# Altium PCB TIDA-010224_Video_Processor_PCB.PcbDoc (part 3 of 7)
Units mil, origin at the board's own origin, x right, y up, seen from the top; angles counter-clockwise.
Board outline 2355.46 x 4164 mil, 10 copper layers (L1-Top Layer, L2-GND, L3-SIG1, L4-GND, L5-PWR, L6-PWR, L7-GND, L8-SIG2, L9-GND, L10-Bottom Layer), stack 62.2 mil thick; 508 components, 274 nets, 3619 pads, 705 vias.
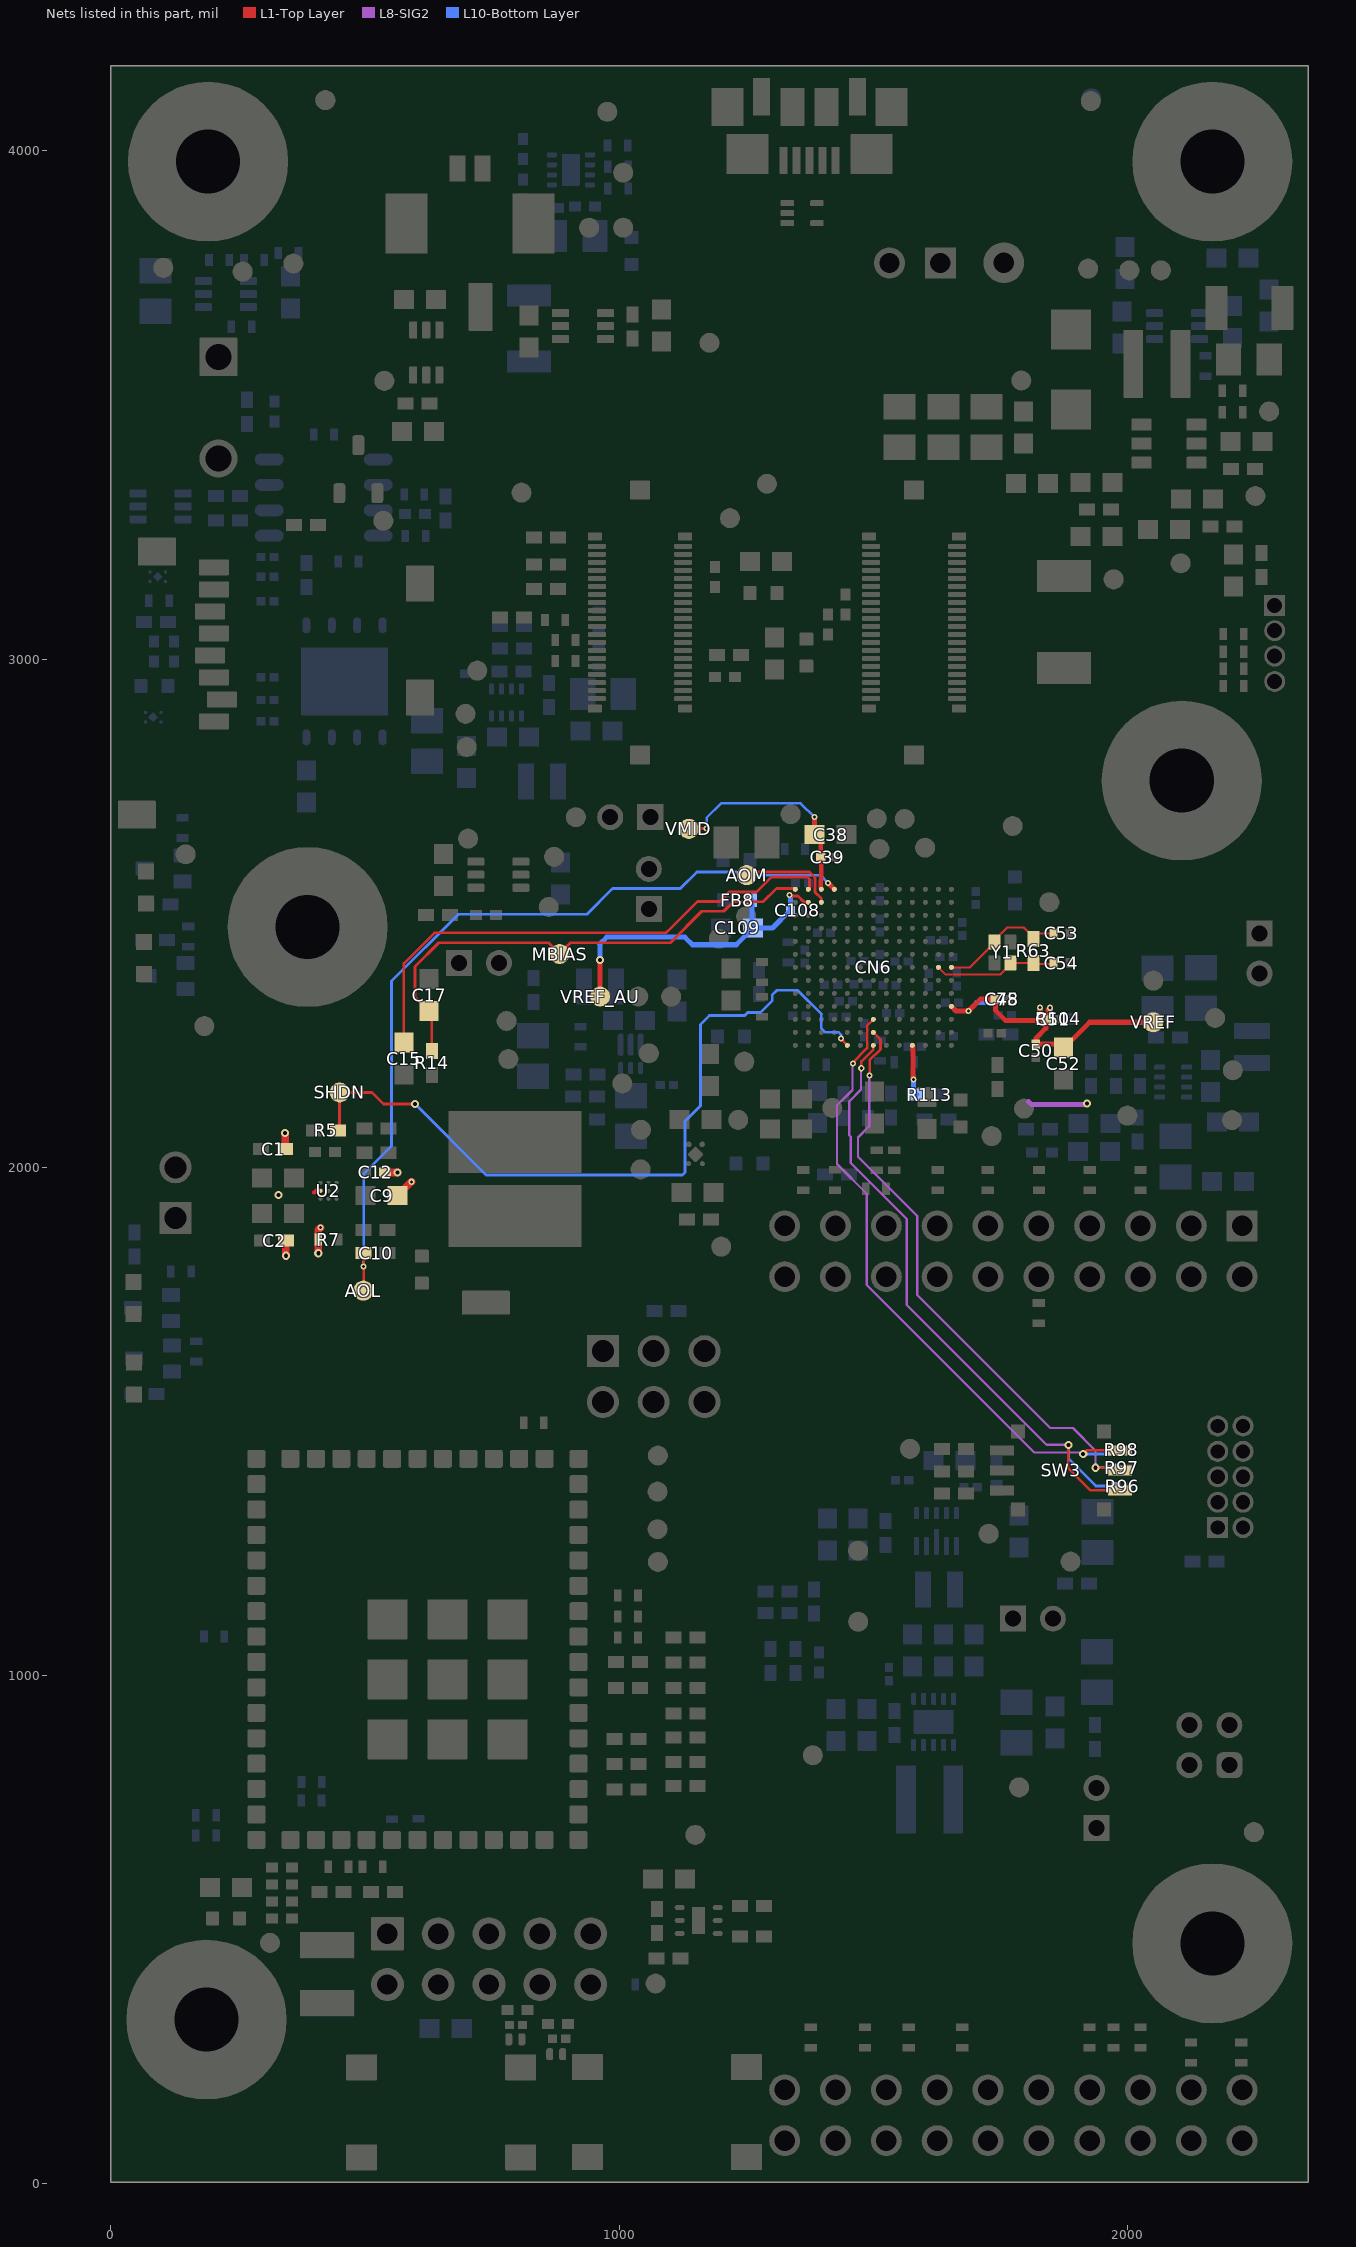
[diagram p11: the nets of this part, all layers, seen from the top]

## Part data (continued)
U4 U10 U19 U20: library part CMP-0081107-1, "5.5-V, 1.5-A, 100-mohm Load Switch with Output Discharge, DCK0006A (SOT-SC70-6)", Alternate Manufacturer="Texas Instruments", Alternate PartNumber=TPS22919DCKR
U6: library part CMP-0085872-1, "Ambient Light Sensor (ALS), DNP0006A (USON-6)", Alternate Manufacturer="Texas Instruments", Alternate PartNumber=OPT3004DNPT
U7: library part CMP-0089990-1, "200-mA, nanopower-IQ (200 nA), low-dropout (LDO) voltage regulator with enable 4-X2SON -40 to 125", Digikey Part Number=296-TPS7A0325PDQNRCT-ND, Dropout Voltage=360mV, Manufacturer="Texas Instruments", Max Supply Voltage=6V, Mouser Part Number=595-TPS7A0325PDQNR, Nominal Supply Current=0.2uA, Operating Temperature Range="-40°C to +125°C", Output Voltage=2.5V
U8: library part CMP-0043096-2, "Low-Capacitance + / - 15 kV ESD-Protection Array for High-Speed Data Interfaces, 2 Channels, -40 to +85 degC, 5-pin SOT (DRL), Green (RoHS & no Sb/Br)", Breakdown Voltage(Min)(V)=11, IO Capacitance(Typ)(pF)=1.5, IO Leakage Current(nA)=1, Manufacturer="Texas Instruments"
U9: library part CMP-0085596-1, "15-V Output Voltage Non-Sync Boost Converter, DBV0006A (SOT-23-6)", Alternate Manufacturer="Texas Instruments", Alternate PartNumber=TLV61048DBVT
U11 U16: library part CMP-0065148-3, "1A Step-Down Converter With 1% Accuracy, DLC0008A (VSON-HR-8)", Alternate Manufacturer="Texas Instruments"
U12: library part CMP-0076712-5, "High Current, High Efficiency Single Inductor Buck-Boost Converter, DLA0010A (VSON-HR-10)", Alternate Manufacturer="Texas Instruments", Alternate PartNumber=TPS63802DLAR, Digikey Part Number=296-TPS63802DLATCT-ND?, Operating Temperature Range="-40 to 125 C"
U13: library part CMP-0086169-2, "TPS63900DSK, DSK0010A (WSON-10)", Alternate Manufacturer="Texas Instruments"
U14: library part CMP-0079420-1, "2-A High Efficiency Synchronous Buck Converter, DMQ0006A (VSON-HR-6)", Alternate Manufacturer="Texas Instruments", Alternate PartNumber=TPS62825DMQT
U15: library part CMP-0013449-3, "1-A Low-Voltage H-Bridge Driver, DSG0008A (WSON-8)", Alternate Manufacturer="Texas Instruments"
U17: library part CMP-0080013-1, "1.8V 128-BIT SERIAL FLASH MEMORY WITH DUAL QUAD SPI & QPI, WSON8", Manufacturer=Macronix, PartNumber=MX25U12835FZNI-10G?, Supplier Part Number 1=1092-1233-ND
U18: library part CMP-0042724-1, "Single MicroPower, Rail-to-Rail, Single Supply Amplifier, 1.8 to 3.6 V, 0 to 70 degC, 8-pin SOIC (D8), Green (RoHS & no Sb/Br)", Manufacturer="Texas Instruments", Rating=Catalog, Total Supply Voltage(Max)(+5V is 5, +/-5V is 10)=3.6, Total Supply Voltage(Min)(+5V is 5, +/-5V is 10)=1.8
U21 U22: library part CMP-0066604-2, "4-Channel ESD Protection With +/-15kV Contact ESD, DPW0004A (X2SON-4)", Alternate Manufacturer="Texas Instruments"
Y1: library part CMP-0089415-1, "Crystals 1.6x1.2 Seam Seal MHz Quartz Xtal -4pad / Ceramic, +/-10ppm @25C, +/-20ppm (-40 to 85C), 8pF", Digikey Part Number=?887-1846-1-ND?, Frequency_Fixed=24MHz, Frequency Stability=20ppm, Frequency Tolerance=10ppm, Load Capacitance=8pF, Manufacturer="TXC Corporation", Mouser Part Number=717-8Q-24.000MEIV-T, Operating Temperature Range="-40°C to +85°C", Part Number=?8Q-24.000MEEV-T?
ZZ1: library part CMP-0077236-1
ZZ2: library part CMP-0077237-1
ZZ3: library part CMP-0077238-1
ZZ4: library part CMP-0003616-3

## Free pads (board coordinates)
  round 0.05 on Mech2: 1(145.48,289.33) 1(145.48,289.33) 1(145.5,290.11) 1(145.5,290.11) 1(145.52,289.33) 1(145.52,289.33) 1(145.54,290.11) 1(145.54,290.11) 1(146.43,290.11) 1(146.43,290.11) 1(146.47,290.11) 1(146.47,290.11)
  round 0.02 on Mech2: 1(145.48,289.65) 1(145.48,289.65) 1(145.48,289.68) 1(145.48,289.68) 1(145.49,289.81) 1(145.49,289.81) 1(145.49,289.93) 1(145.49,289.93) 1(145.49,290.05) 1(145.49,290.05) 1(145.49,289.75) 1(145.49,289.75) 1(145.5,289.58) 1(145.5,289.58) 1(145.5,289.09) 1(145.5,289.09) 1(145.51,289.06) 1(145.51,289.06) 1(145.51,289.61) 1(145.51,289.61) 1(145.51,289.63) 1(145.51,289.63) 1(145.51,289.7) 1(145.51,289.7) 1(145.51,289.72) 1(145.51,289.72) 1(145.51,289.77) 1(145.51,289.77) 1(145.51,289.79) 1(145.51,289.79) 1(145.51,289.82) 1(145.51,289.82) 1(145.52,289.47) 1(145.52,289.47) 1(145.53,289.51) 1(145.53,289.51) 1(145.53,289.55) 1(145.53,289.55) 1(145.53,289.59) 1(145.53,289.59) 1(145.53,289.64) 1(145.53,289.64) 1(145.53,289.69) 1(145.53,289.69) 1(145.53,289.74) 1(145.53,289.74) 1(145.53,289.06) 1(145.53,289.06) 1(145.53,289.09) 1(145.53,289.09) 1(145.54,289.45) 1(145.54,289.45) 1(145.56,289.84) 1(145.56,289.84) 1(145.57,289.19) 1(145.59,290.14) 1(145.59,290.14) 1(145.59,289.4) 1(145.59,289.4) 1(145.6,289.86) 1(145.6,289.86) 1(145.6,289.19) 1(145.6,289.19) 1(145.62,289.13) 1(145.62,289.13) 1(145.62,289.18) 1(145.62,289.18) 1(145.63,289.09) 1(145.63,289.09) 1(145.63,289.12) 1(145.63,289.12) 1(145.63,289.38) 1(145.63,289.38) 1(145.63,289.91) 1(145.63,289.91) 1(145.64,289.24) 1(145.64,289.24) 1(145.64,289.27) 1(145.64,289.27) 1(145.64,289.27) 1(145.66,289.22) 1(145.66,289.22) 1(145.67,289.06) 1(145.67,289.06) 1(145.67,289.08) 1(145.67,289.08) 1(145.67,289.09) 1(145.67,289.86) 1(145.67,289.86) 1(145.68,289.42) 1(145.68,289.42) 1(145.69,289.25) 1(145.69,289.25) 1(145.69,289.27) 1(145.69,289.27) 1(145.69,289.27) 1(145.7,289.06) 1(145.7,289.06) 1(145.7,289.08) 1(145.7,289.08) 1(145.71,289.84) 1(145.71,289.84) 1(145.72,290.14) 1(145.72,290.14) 1(145.72,289.06) 1(145.72,289.06) 1(145.75,289.48) 1(145.75,289.48) 1(145.75,289.82) 1(145.75,289.82) 1(145.75,289.32) 1(145.75,289.32) 1(145.75,289.06) 1(145.75,289.06) 1(145.75,289.37) 1(145.75,289.37) 1(145.78,289.3) 1(145.78,289.3) 1(145.78,289.44) 1(145.78,289.44) 1(145.78,289.21) 1(145.8,289.52) 1(145.8,289.52) 1(145.81,289.35) 1(145.81,289.35) 1(145.81,289.5) 1(145.81,289.5) 1(145.83,289.21) 1(145.83,289.21) 1(145.83,289.21) 1(145.83,289.08) 1(145.83,289.08) 1(145.83,289.06) 1(145.83,289.06) 1(145.85,289.05) 1(145.85,289.05) 1(145.85,289.07) 1(145.85,289.07) 1(145.85,289.35) 1(145.85,289.35) 1(145.85,290.14) 1(145.85,290.14) 1(145.86,289.81) 1(145.86,289.81) 1(145.88,289.37) 1(145.88,289.37) 1(145.89,289.5) 1(145.89,289.5) 1(145.89,289.53) 1(145.89,289.53) 1(145.89,289.81) 1(145.89,289.81) 1(145.89,289.13) 1(145.89,289.13) 1(145.91,289.53) 1(145.91,289.53) 1(145.92,289.44) 1(145.92,289.44) 1(145.92,289.49) 1(145.92,289.49) 1(145.92,289.13) 1(145.92,289.13) 1(145.93,289.81) 1(145.93,289.81) 1(145.94,289.44) 1(145.94,289.44) 1(145.94,289.49) 1(145.94,289.49) 1(145.95,289.17) 1(145.95,289.17) 1(145.95,289.13) 1(145.95,289.13) 1(145.95,289.15) 1(145.95,289.15) 1(145.98,289.48) 1(145.98,289.48) 1(145.98,289.09) 1(145.98,289.09) 1(145.99,290.14) 1(145.99,290.14) 1(146,289.3) 1(146,289.3) 1(146.01,289.2) 1(146.01,289.2) 1(146.01,289.26) 1(146.01,289.26) 1(146.02,289.57) 1(146.02,289.39) 1(146.02,289.39) 1(146.02,289.48) 1(146.02,289.48) 1(146.04,289.57) 1(146.04,289.57) 1(146.04,289.77) 1(146.04,289.77) 1(146.06,289.48) 1(146.06,289.48) 1(146.06,289.82) 1(146.06,289.82) 1(146.06,289.15) 1(146.06,289.15) 1(146.07,289.3) 1(146.07,289.3) 1(146.09,289.13) 1(146.09,289.13) 1(146.09,289.18) 1(146.09,289.18) 1(146.1,289.45) 1(146.1,289.45) 1(146.1,289.84) 1(146.1,289.84) 1(146.11,289.64) 1(146.11,289.64) 1(146.11,289.31) 1(146.11,289.31) 1(146.12,290.14) 1(146.12,290.14) 1(146.12,289.18) 1(146.12,289.18) 1(146.13,289.44) 1(146.13,289.44) 1(146.13,289.86) 1(146.13,289.86) 1(146.14,289.32) 1(146.14,289.32) 1(146.17,289.91) 1(146.17,289.91) 1(146.18,289.18) 1(146.18,289.18) 1(146.2,289.25) 1(146.2,289.25) 1(146.21,289.86) 1(146.21,289.86) 1(146.22,289.44) 1(146.22,289.44) 1(146.25,289.45) 1(146.25,289.45) 1(146.25,289.84) 1(146.25,289.84) 1(146.25,290.14) 1(146.25,290.14) 1(146.26,289.06) 1(146.26,289.06) 1(146.29,289.48) 1(146.29,289.48) 1(146.29,289.82) 1(146.29,289.82) 1(146.33,289.64) 1(146.33,289.69) 1(146.33,289.73) 1(146.33,289.73) 1(146.33,289.73) 1(146.35,289.13) 1(146.35,289.13) 1(146.36,289.37) 1(146.36,289.37) 1(146.38,289.06) 1(146.38,289.06) 1(146.38,290.14) 1(146.38,290.14) 1(146.45,289.43) 1(146.45,289.43) 1(146.47,289.13) 1(146.47,289.13) 1(146.48,289.36) 1(146.48,289.36) 1(146.49,289.67) 1(146.49,289.67) 1(146.49,289.93) 1(146.49,289.93) 1(146.49,290.06) 1(146.49,290.06)
  round 0 on Mech2: 1(145.48,289.65) 1(145.48,289.65) 1(145.48,289.68) 1(145.48,289.68) 1(145.49,289.66) 1(145.49,289.66) 1(145.49,289.66) 1(145.49,289.66) 1(145.49,289.67) 1(145.49,289.67) 1(145.49,289.67) 1(145.49,289.67) 1(145.51,289.61) 1(145.51,289.61) 1(145.51,289.63) 1(145.51,289.63) 1(145.51,289.7) 1(145.51,289.7) 1(145.51,289.72) 1(145.51,289.72) 1(145.51,289.61) 1(145.51,289.61) 1(145.51,289.61) 1(145.51,289.61) 1(145.51,289.62) 1(145.51,289.62) 1(145.51,289.62) 1(145.51,289.62) 1(145.51,289.71) 1(145.51,289.71) 1(145.51,289.71) 1(145.51,289.71) 1(145.51,289.72) 1(145.51,289.72) 1(145.51,289.72) 1(145.51,289.72) 1(145.53,289.61) 1(145.53,289.61) 1(145.53,289.62) 1(145.53,289.62) 1(145.53,289.66) 1(145.53,289.66) 1(145.53,289.67) 1(145.53,289.67) 1(145.53,289.71) 1(145.53,289.71) 1(145.53,289.72) 1(145.53,289.72) 1(145.53,289.61) 1(145.53,289.61) 1(145.53,289.62) 1(145.53,289.62) 1(145.53,289.66) 1(145.53,289.66) 1(145.53,289.67) 1(145.53,289.67) 1(145.53,289.7) 1(145.53,289.7) 1(145.53,289.72) 1(145.53,289.72) 1(145.54,289.72) 1(145.54,289.72) 1(145.54,289.47) 1(145.54,289.48) 1(145.54,289.81) 1(145.54,289.82) 1(145.55,289.71) 1(145.55,289.71) 1(145.55,289.61) 1(145.55,289.61) 1(145.55,289.15) 1(145.55,289.16) 1(145.55,289.18) 1(145.55,289.2) 1(145.55,289.22) 1(145.55,289.24) 1(145.55,289.62) 1(145.55,289.62) 1(145.56,289.74) 1(145.56,289.74) 1(145.56,289.61) 1(145.56,289.62) 1(145.56,289.66) 1(145.56,289.67) 1(145.56,289.7) 1(145.56,289.72) 1(145.56,289.72) 1(145.56,289.72) 1(145.57,289.66) 1(145.57,289.66) 1(145.57,289.59) 1(145.57,289.59) 1(145.57,289.72) 1(145.57,289.72) 1(145.57,289.64) 1(145.57,289.64) 1(145.57,289.65) 1(145.57,289.65) 1(145.57,289.67) 1(145.57,289.67) 1(145.57,289.6) 1(145.57,289.6) 1(145.58,289.47) 1(145.58,289.48) 1(145.58,289.81) 1(145.58,289.82) 1(145.58,289.74) 1(145.58,289.74) 1(145.58,289.63) 1(145.58,289.63) 1(145.58,289.65) 1(145.58,289.65) 1(145.58,289.66) 1(145.58,289.66) 1(145.59,289.15) 1(145.59,289.16) 1(145.59,289.18) 1(145.59,289.2) 1(145.59,289.22) 1(145.59,289.24) 1(145.59,289.64) 1(145.59,289.64) 1(145.59,289.7) 1(145.59,289.7) 1(145.6,289.72) 1(145.6,289.72) 1(145.6,289.64) 1(145.6,289.64) 1(145.6,289.65) 1(145.6,289.65) 1(145.6,289.66) 1(145.6,289.66) 1(145.6,289.63) 1(145.6,289.63) 1(145.61,289.72) 1(145.61,289.72) 1(145.61,289.67) 1(145.61,289.67) 1(145.61,289.64) 1(145.61,289.64) 1(145.61,289.65) 1(145.61,289.65) 1(145.62,289.7) 1(145.62,289.7) 1(145.62,289.66) 1(145.62,289.66) 1(145.63,289.66) 1(145.63,289.66) 1(145.63,289.74) 1(145.63,289.74) 1(145.63,289.64) 1(145.63,289.64) 1(145.63,289.65) 1(145.63,289.65) 1(145.64,289.67) 1(145.64,289.67) 1(145.64,289.73) 1(145.64,289.73) 1(145.65,289.63) 1(145.65,289.63) 1(145.65,289.65) 1(145.65,289.65) 1(145.65,289.66) 1(145.65,289.66) 1(145.65,289.65) 1(145.65,289.65) 1(145.66,289.15) 1(145.66,289.16) 1(145.66,289.22) 1(145.66,289.24) 1(145.66,289.65) 1(145.66,289.65) 1(145.67,289.63) 1(145.67,289.63) 1(145.67,289.65) 1(145.67,289.65) 1(145.67,289.68) 1(145.67,289.68) 1(145.68,289.65) 1(145.68,289.65) 1(145.68,289.67) 1(145.68,289.67) 1(145.68,289.69) 1(145.68,289.69) 1(145.68,289.68) 1(145.68,289.68) 1(145.69,289.47) 1(145.69,289.48) 1(145.69,289.81) 1(145.69,289.82) 1(145.69,289.15) 1(145.69,289.16) 1(145.69,289.22) 1(145.69,289.24) 1(145.71,289.73) 1(145.71,289.73) 1(145.71,289.68) 1(145.71,289.68) 1(145.71,289.71) 1(145.71,289.71) 1(145.71,289.72) 1(145.71,289.72) 1(145.71,289.66) 1(145.71,289.66) 1(145.71,289.67) 1(145.71,289.67) 1(145.71,289.71) 1(145.71,289.71) 1(145.72,289.6) 1(145.72,289.6) 1(145.72,289.66) 1(145.72,289.66) 1(145.72,289.61) 1(145.72,289.61) 1(145.72,289.61) 1(145.72,289.61) 1(145.72,289.47) 1(145.72,289.48) 1(145.72,289.81) 1(145.72,289.82) 1(145.72,289.62) 1(145.72,289.62) 1(145.73,289.71) 1(145.73,289.71) 1(145.73,289.66) 1(145.73,289.66) 1(145.73,289.71) 1(145.73,289.71) 1(145.73,289.72) 1(145.73,289.72) 1(145.73,289.62) 1(145.73,289.62) 1(145.73,289.66) 1(145.73,289.66) 1(145.73,289.67) 1(145.73,289.67) 1(145.73,289.73) 1(145.73,289.73) 1(145.73,289.61) 1(145.73,289.61) 1(145.73,289.61) 1(145.73,289.61) 1(145.73,289.68) 1(145.73,289.68) 1(145.74,289.6) 1(145.74,289.6) 1(145.74,289.68) 1(145.74,289.68) 1(145.74,289.69) 1(145.74,289.69) 1(145.74,289.73) 1(145.74,289.73) 1(145.75,289.67) 1(145.75,289.67) 1(145.75,289.69) 1(145.75,289.69) 1(145.75,289.72) 1(145.75,289.72) 1(145.75,289.74) 1(145.75,289.74) 1(145.75,289.6) 1(145.75,289.6) 1(145.75,289.59) 1(145.75,289.59) 1(145.75,289.68) 1(145.75,289.68) 1(145.75,289.69) 1(145.75,289.69) 1(145.75,289.73) 1(145.75,289.73) 1(145.75,289.74) 1(145.75,289.74) 1(145.75,289.59) 1(145.75,289.59) 1(145.75,289.61) 1(145.75,289.61) 1(145.76,289.59) 1(145.76,289.59) 1(145.76,289.6) 1(145.76,289.6) 1(145.76,289.68) 1(145.76,289.68) 1(145.76,289.69) 1(145.76,289.69) 1(145.77,289.6) 1(145.77,289.6) 1(145.77,289.61) 1(145.77,289.61) 1(145.77,289.61) 1(145.77,289.61) 1(145.77,289.66) 1(145.77,289.66) 1(145.77,289.61) 1(145.77,289.61) 1(145.78,289.67) 1(145.78,289.67) 1(145.78,289.61) 1(145.78,289.61) 1(145.78,289.61) 1(145.78,289.61) 1(145.78,289.61) 1(145.78,289.61) 1(145.79,289.73) 1(145.79,289.73) 1(145.79,289.6) 1(145.79,289.6) 1(145.79,289.69) 1(145.79,289.69) 1(145.79,289.74) 1(145.79,289.74) 1(145.79,289.7) 1(145.79,289.7) 1(145.79,289.72) 1(145.79,289.72) 1(145.8,289.68) 1(145.81,289.7) 1(145.81,289.7) 1(145.81,289.72) 1(145.81,289.72) 1(145.81,289.66) 1(145.81,289.66) 1(145.81,289.66) 1(145.81,289.66) 1(145.81,289.69) 1(145.81,289.69) 1(145.82,289.67) 1(145.82,289.67) 1(145.82,289.65) 1(145.82,289.68) 1(145.83,289.6) 1(145.83,289.6) 1(145.83,289.66) 1(145.83,289.66) 1(145.83,289.66) 1(145.83,289.66) 1(145.83,289.59) 1(145.83,289.59) 1(145.84,289.65) 1(145.84,289.68) 1(145.85,289.66) 1(145.85,289.66) 1(145.85,289.67) 1(145.85,289.67) 1(145.85,289.68) 1(145.85,289.68) 1(145.85,289.69) 1(145.85,289.69) 1(145.86,289.67) 1(145.86,289.67) 1(145.86,289.68) 1(145.86,289.68) 1(145.86,289.68) 1(145.87,289.67) 1(145.87,289.67) 1(145.87,289.68) 1(145.87,289.68) 1(145.87,289.65) 1(145.87,289.65) 1(145.87,289.66) 1(145.87,289.66) 1(145.88,289.64) 1(145.88,289.64) 1(145.88,289.67) 1(145.88,289.67) 1(146.08,289.2) 1(146.08,289.2) 1(146.08,289.22) 1(146.08,289.22) 1(146.08,289.24) 1(146.08,289.24) 1(146.08,289.26) 1(146.08,289.26) 1(146.08,289.47) 1(146.08,289.48) 1(146.08,289.81) 1(146.08,289.82) 1(146.09,289.2) 1(146.09,289.2) 1(146.09,289.22) 1(146.09,289.22) 1(146.09,289.24) 1(146.09,289.24) 1(146.09,289.26) 1(146.09,289.26) 1(146.11,289.47) 1(146.11,289.48) 1(146.11,289.81) 1(146.11,289.82) 1(146.15,289.2) 1(146.15,289.2) 1(146.15,289.22) 1(146.15,289.22) 1(146.15,289.24) 1(146.15,289.24) 1(146.15,289.26) 1(146.15,289.26) 1(146.17,289.2) 1(146.17,289.2) 1(146.17,289.22) 1(146.17,289.22) 1(146.17,289.24) 1(146.17,289.24) 1(146.17,289.26) 1(146.17,289.26) 1(146.23,289.47) 1(146.23,289.48) 1(146.23,289.81) 1(146.23,289.82) 1(146.26,289.47) 1(146.26,289.48) 1(146.26,289.81) 1(146.26,289.82)
  round 0.02 on Mech4: 1(145.48,289.65) 1(145.48,289.68) 1(145.49,289.81) 1(145.49,289.93) 1(145.49,290.05) 1(145.49,289.75) 1(145.5,289.58) 1(145.5,289.09) 1(145.51,289.06) 1(145.51,289.61) 1(145.51,289.63) 1(145.51,289.7) 1(145.51,289.72) 1(145.51,289.77) 1(145.51,289.79) 1(145.51,289.82) 1(145.52,289.47) 1(145.53,289.51) 1(145.53,289.55) 1(145.53,289.59) 1(145.53,289.64) 1(145.53,289.69) 1(145.53,289.74) 1(145.53,289.06) 1(145.53,289.09) 1(145.54,289.45) 1(145.56,289.84) 1(145.59,290.14) 1(145.59,289.4) 1(145.6,289.86) 1(145.63,289.38) 1(145.63,289.91) 1(145.64,289.27) 1(145.67,289.06) 1(145.67,289.08) 1(145.67,289.86) 1(145.68,289.42) 1(145.69,289.27) 1(145.7,289.06) 1(145.7,289.08) 1(145.71,289.84) 1(145.72,290.14) 1(145.72,289.06) 1(145.75,289.48) 1(145.75,289.82) 1(145.75,289.32) 1(145.75,289.06) 1(145.75,289.37) 1(145.78,289.3) 1(145.78,289.44) 1(145.8,289.52) 1(145.81,289.35) 1(145.81,289.5) 1(145.83,289.21) 1(145.83,289.08) 1(145.83,289.06) 1(145.85,289.05) 1(145.85,289.07) 1(145.85,289.35) 1(145.85,290.14) 1(145.86,289.81) 1(145.88,289.37) 1(145.89,289.5) 1(145.89,289.53) 1(145.89,289.81) 1(145.89,289.13) 1(145.91,289.53) 1(145.92,289.44) 1(145.92,289.49) 1(145.92,289.13) 1(145.93,289.81) 1(145.94,289.44) 1(145.94,289.49) 1(145.95,289.17) 1(145.95,289.13) 1(145.95,289.15) 1(145.98,289.48) 1(145.98,289.09) 1(145.99,290.14) 1(146,289.3) 1(146.01,289.2) 1(146.01,289.26) 1(146.02,289.39) 1(146.02,289.48) 1(146.04,289.77) 1(146.06,289.48) 1(146.06,289.82) 1(146.06,289.15) 1(146.07,289.3) 1(146.09,289.13) 1(146.09,289.18) 1(146.1,289.45) 1(146.1,289.84) 1(146.11,289.31) 1(146.12,290.14) 1(146.12,289.18) 1(146.13,289.44) 1(146.13,289.86) 1(146.14,289.32) 1(146.17,289.91) 1(146.18,289.18) 1(146.2,289.25) 1(146.21,289.86) 1(146.22,289.44) 1(146.25,289.45) 1(146.25,289.84) 1(146.25,290.14) 1(146.26,289.06) 1(146.29,289.48) 1(146.29,289.82) 1(146.33,289.73) 1(146.35,289.13) 1(146.36,289.37) 1(146.38,289.06) 1(146.38,290.14) 1(146.45,289.43) 1(146.47,289.13) 1(146.48,289.36) 1(146.49,289.67) 1(146.49,289.93) 1(146.49,290.06)
  round 0.01 on Mech2: 1(145.51,289.77) 1(145.51,289.77) 1(145.51,289.77) 1(145.51,289.79) 1(145.51,289.81) 1(145.51,289.81) 1(145.51,289.82) 1(145.52,289.78) 1(145.52,289.78) 1(145.52,289.47) 1(145.52,289.49) 1(145.52,289.49) 1(145.53,289.55) 1(145.53,289.64) 1(145.53,289.69) 1(145.53,289.74) 1(145.53,289.5) 1(145.53,289.5) 1(145.53,289.8) 1(145.53,289.8) 1(145.53,289.5) 1(145.53,289.5) 1(145.53,289.5) 1(145.53,289.5) 1(145.56,289.5) 1(145.56,289.74) 1(145.56,289.74) 1(145.56,289.55) 1(145.56,289.64) 1(145.56,289.69) 1(145.56,289.73) 1(145.56,289.77) 1(145.56,289.78) 1(145.56,289.8) 1(145.56,289.15) 1(145.56,289.15) 1(145.56,289.16) 1(145.57,289.09) 1(145.57,289.15) 1(145.57,289.15) 1(145.58,289.17) 1(145.6,289.18) 1(145.6,289.18) 1(145.61,289.16) 1(145.61,289.18) 1(145.61,289.18) 1(145.62,289.18) 1(145.62,289.18) 1(145.66,289.16) 1(145.66,289.16) 1(145.66,289.16) 1(145.66,289.22) 1(145.71,289.5) 1(145.71,289.8) 1(145.74,289.5) 1(145.74,289.5) 1(145.74,289.8) 1(145.74,289.8) 1(145.75,289.48) 1(145.75,289.49) 1(145.75,289.49) 1(145.75,289.8) 1(145.75,289.8) 1(145.75,289.82) 1(145.75,289.32) 1(145.75,289.63) 1(145.75,289.63) 1(145.75,289.63) 1(145.75,289.63) 1(145.75,289.67) 1(145.75,289.67) 1(145.75,289.69) 1(145.75,289.69) 1(145.75,289.72) 1(145.75,289.72) 1(145.75,289.74) 1(145.75,289.74) 1(145.75,289.59) 1(145.75,289.59) 1(145.75,289.61) 1(145.75,289.61) 1(145.76,289.33) 1(145.76,289.33) 1(145.76,289.65) 1(145.76,289.65) 1(145.77,289.63) 1(145.77,289.63) 1(145.77,289.63) 1(145.78,289.75) 1(145.78,289.75) 1(145.78,289.75) 1(145.78,289.58) 1(145.78,289.62) 1(145.78,289.65) 1(145.78,289.65) 1(145.78,289.68) 1(145.78,289.71) 1(145.78,289.75) 1(145.78,289.75) 1(145.78,289.75) 1(145.78,289.75) 1(145.78,289.3) 1(145.78,289.33) 1(145.78,289.33) 1(145.78,289.37) 1(145.79,289.57) 1(145.79,289.57) 1(145.79,289.57) 1(145.79,289.57) 1(145.79,289.63) 1(145.79,289.63) 1(145.79,289.63) 1(145.79,289.63) 1(145.79,289.63) 1(145.79,289.69) 1(145.79,289.69) 1(145.8,289.58) 1(145.8,289.62) 1(145.8,289.65) 1(145.8,289.68) 1(145.8,289.71) 1(145.8,289.58) 1(145.8,289.62) 1(145.8,289.65) 1(145.8,289.71) 1(145.8,289.72) 1(145.8,289.72) 1(145.81,289.63) 1(145.81,289.63) 1(145.81,289.63) 1(145.81,289.54) 1(145.81,289.54) 1(145.81,289.57) 1(145.81,289.57) 1(145.81,289.57) 1(145.81,289.57) 1(145.81,289.57) 1(145.81,289.66) 1(145.81,289.66) 1(145.81,289.69) 1(145.81,289.69) 1(145.81,289.35) 1(145.81,289.37) 1(145.81,289.37) 1(145.81,289.5) 1(145.81,289.37) 1(145.81,289.37) 1(145.82,289.63) 1(145.82,289.63) 1(145.82,289.53) 1(145.82,289.53) 1(145.82,289.74) 1(145.82,289.58) 1(145.82,289.58) 1(145.82,289.62) 1(145.82,289.65) 1(145.82,289.68) 1(145.82,289.71) 1(145.82,289.74) 1(145.82,289.74) 1(145.82,289.74) 1(145.82,289.74) 1(145.82,289.74) 1(145.82,289.74) 1(145.82,289.74) 1(145.83,289.63) 1(145.83,289.57) 1(145.83,289.57) 1(145.83,289.57) 1(145.83,289.57) 1(145.83,289.63) 1(145.83,289.63) 1(145.83,289.66) 1(145.83,289.66) 1(145.83,289.5) 1(145.83,289.5) 1(145.83,289.53) 1(145.83,289.53) 1(145.84,289.58) 1(145.84,289.71) 1(145.84,289.72) 1(145.84,289.72) 1(145.85,289.35) 1(145.85,289.37) 1(145.85,289.37) 1(145.85,289.37) 1(145.85,289.37) 1(145.85,289.57) 1(145.85,289.57) 1(145.85,289.57) 1(145.85,289.57) 1(145.85,289.57) 1(145.85,289.66) 1(145.85,289.66) 1(145.85,289.69) 1(145.85,289.69) 1(145.86,289.72) 1(145.86,289.72) 1(145.86,289.75) 1(145.86,289.79) 1(145.86,289.79) 1(145.86,289.81) 1(145.86,289.58) 1(145.86,289.62) 1(145.86,289.65) 1(145.86,289.68) 1(145.86,289.71) 1(145.86,289.58) 1(145.86,289.71) 1(145.86,289.72) 1(145.86,289.72) 1(145.86,289.72) 1(145.86,289.72) 1(145.87,289.57) 1(145.87,289.57) 1(145.87,289.5) 1(145.87,289.5) 1(145.87,289.53) 1(145.87,289.53) 1(145.87,289.53) 1(145.87,289.57) 1(145.87,289.57) 1(145.87,289.53) 1(145.87,289.53) 1(145.87,289.57) 1(145.87,289.57) 1(145.87,289.6) 1(145.87,289.6) 1(145.87,289.6) 1(145.88,289.37) 1(145.88,289.58) 1(145.88,289.58) 1(145.88,289.62) 1(145.88,289.65) 1(145.88,289.68) 1(145.88,289.71) 1(145.89,289.5) 1(145.89,289.53) 1(145.89,289.79) 1(145.89,289.79) 1(145.89,289.6) 1(145.89,289.6) 1(145.89,289.6) 1(145.89,289.71) 1(145.89,289.71) 1(145.89,289.75) 1(145.89,289.75) 1(145.89,289.79) 1(145.89,289.79) 1(145.89,289.79) 1(145.89,289.81) 1(145.9,289.58) 1(145.9,289.58) 1(145.9,289.62) 1(145.9,289.65) 1(145.9,289.68) 1(145.9,289.71) 1(145.9,289.71) 1(145.91,289.57) 1(145.91,289.6) 1(145.91,289.6) 1(145.91,289.6) 1(145.91,289.6) 1(145.91,289.63) 1(145.91,289.63) 1(145.91,289.69) 1(145.91,289.69) 1(145.91,289.69) 1(145.91,289.69) 1(145.91,289.69) 1(145.91,289.53) 1(145.91,289.57) 1(145.91,289.57) 1(145.92,289.66) 1(145.92,289.69) 1(145.92,289.69) 1(145.92,289.58) 1(145.92,289.62) 1(145.92,289.65) 1(145.92,289.68) 1(145.92,289.71) 1(145.92,289.58) 1(145.92,289.68) 1(145.93,289.69) 1(145.93,289.69) 1(145.93,289.75) 1(145.93,289.75) 1(145.93,289.79) 1(145.93,289.79) 1(145.93,289.79) 1(145.93,289.81) 1(145.93,289.63) 1(145.93,289.63) 1(145.93,289.69) 1(145.93,289.69) 1(145.93,289.69) 1(145.93,289.69) 1(145.94,289.58) 1(145.94,289.58) 1(145.94,289.62) 1(145.94,289.65) 1(145.94,289.65) 1(145.94,289.68) 1(145.94,289.71) 1(145.96,289.57) 1(145.96,289.57) 1(145.96,289.57) 1(145.96,289.57) 1(145.96,289.6) 1(145.96,289.6) 1(145.96,289.6) 1(145.96,289.63) 1(145.96,289.63) 1(145.96,289.63) 1(145.96,289.69) 1(145.96,289.69) 1(145.96,289.69) 1(145.97,289.79) 1(145.97,289.79) 1(145.97,289.58) 1(145.97,289.58) 1(145.97,289.62) 1(145.97,289.62) 1(145.97,289.65) 1(145.97,289.68) 1(145.97,289.68) 1(145.97,289.71) 1(145.97,289.79) 1(145.97,289.79) 1(145.98,289.63) 1(145.98,289.63) 1(145.98,289.69) 1(145.98,289.69) 1(145.99,289.58) 1(145.99,289.62) 1(145.99,289.65) 1(145.99,289.68) 1(145.99,289.71) 1(145.99,289.62) 1(145.99,289.65) 1(145.99,289.71) 1(146,289.6) 1(146,289.6) 1(146,289.6) 1(146,289.6) 1(146,289.6) 1(146,289.63) 1(146,289.63) 1(146,289.63) 1(146,289.63) 1(146,289.66) 1(146,289.66) 1(146,289.69) 1(146,289.69) 1(146,289.69) 1(146,289.69) 1(146,289.69) 1(146,289.72) 1(146,289.72) 1(146,289.66) 1(146,289.69) 1(146,289.69) 1(146,289.79) 1(146,289.59) 1(146,289.59) 1(146.01,289.58) 1(146.01,289.58) 1(146.01,289.62) 1(146.01,289.62) 1(146.01,289.65) 1(146.01,289.68) 1(146.01,289.68) 1(146.01,289.71) 1(146.01,289.49) 1(146.01,289.49) 1(146.01,289.51) 1(146.01,289.55) 1(146.02,289.55) 1(146.02,289.55) 1(146.02,289.57) 1(146.02,289.57) 1(146.02,289.57) 1(146.02,289.57) 1(146.02,289.63) 1(146.02,289.63) 1(146.02,289.63) 1(146.02,289.48) 1(146.03,289.69) 1(146.03,289.69) 1(146.04,289.66) 1(146.04,289.68) 1(146.04,289.68) 1(146.04,289.63) 1(146.04,289.63) 1(146.04,289.59) 1(146.04,289.63) 1(146.09,289.2) 1(146.09,289.26) 1(146.09,289.18) 1(146.09,289.18) 1(146.09,289.2) 1(146.09,289.2) 1(146.11,289.16) 1(146.11,289.16) 1(146.12,289.26) 1(146.12,289.26) 1(146.12,289.25) 1(146.16,289.16) 1(146.16,289.16) 1(146.16,289.16) 1(146.16,289.16) 1(146.16,289.2) 1(146.16,289.2) 1(146.16,289.16) 1(146.16,289.2) 1(146.16,289.2) 1(146.17,289.2) 1(146.17,289.2) 1(146.18,289.18) 1(146.18,289.18) 1(146.18,289.18) 1(146.18,289.18) 1(146.18,289.19) 1(146.18,289.19) 1(146.18,289.19) 1(146.18,289.19)
  round 0.01 on Mech4: 1(145.75,289.63) 1(145.75,289.67) 1(145.75,289.69) 1(145.75,289.72) 1(145.75,289.74) 1(145.75,289.59) 1(145.75,289.61) 1(145.77,289.66) 1(145.78,289.74) 1(145.78,289.74) 1(145.78,289.75) 1(145.78,289.75) 1(145.79,289.66) 1(145.79,289.66) 1(145.79,289.57) 1(145.79,289.63) 1(145.79,289.69) 1(145.81,289.71) 1(145.81,289.71) 1(145.81,289.57) 1(145.81,289.66) 1(145.81,289.69) 1(145.82,289.63) 1(145.82,289.63) 1(145.82,289.74) 1(145.83,289.63) 1(145.83,289.57) 1(145.83,289.63) 1(145.83,289.66) 1(145.85,289.57) 1(145.85,289.66) 1(145.85,289.69) 1(145.86,289.71) 1(145.86,289.71) 1(145.86,289.72) 1(145.87,289.6) 1(145.87,289.6) 1(145.87,289.7) 1(145.87,289.7) 1(145.89,289.6) 1(145.91,289.6) 1(145.91,289.63) 1(145.91,289.69) 1(145.93,289.63) 1(145.93,289.69) 1(145.96,289.57) 1(145.96,289.6) 1(145.96,289.63) 1(145.96,289.69) 1(145.98,289.63) 1(145.98,289.69) 1(145.98,289.58) 1(145.98,289.6) 1(145.98,289.6) 1(146,289.6) 1(146,289.62) 1(146,289.62) 1(146,289.63) 1(146,289.63) 1(146,289.63) 1(146,289.65) 1(146,289.69) 1(146,289.72) 1(146.02,289.57) 1(146.02,289.63)
  round 10 on Mech16: 1(860.32,2621.8) 1(860.32,2621.8) 1(860.32,2621.8) 1(860.32,3621.33) 1(860.32,3621.33) 1(860.32,3621.33) 1(866.32,3651.46) 1(866.32,3651.46) 1(866.32,3651.46) 1(866.32,3651.46) 1(866.32,2591.67) 1(866.32,2591.67) 1(866.32,2591.67) 1(866.32,2591.67) 1(883.38,3677.01) 1(883.38,3677.01) 1(883.38,3677.01) 1(883.38,3677.01) 1(883.39,2566.13) 1(883.39,2566.13) 1(883.39,2566.13) 1(883.39,2566.13) 1(908.93,3694.08) 1(908.93,3694.08) 1(908.93,3694.08) 1(908.93,3694.08) 1(908.94,2549.06) 1(909.71,2548.54) 1(909.71,2548.54) 1(939.06,3700.08) 1(939.06,3700.08) 1(939.07,3700.06) 1(939.53,2542.61) 1(939.53,2542.61) 1(1854.59,2542.61) 1(1854.59,2542.61) 1(1854.59,2542.61) 1(1854.59,3700.06) 1(1854.59,3700.06) 1(1854.59,3700.06) 1(1884.73,2548.6) 1(1884.73,2548.6) 1(1884.73,2548.6) 1(1884.73,2548.6) 1(1884.73,3694.07) 1(1884.73,3694.07) 1(1884.73,3694.07) 1(1884.73,3694.07) 1(1910.28,2565.67) 1(1910.28,2565.67) 1(1910.28,2565.67) 1(1910.28,2565.67) 1(1910.28,3677) 1(1910.28,3677) 1(1910.28,3677) 1(1910.28,3677) 1(1927.35,2591.22) 1(1927.35,2591.22) 1(1927.35,2591.22) 1(1927.35,2591.22) 1(1927.35,3651.46) 1(1927.35,3651.46) 1(1927.35,3651.46) 1(1927.35,3651.46) 1(1933.34,2621.35) 1(1933.34,2621.35) 1(1933.34,2621.35) 1(1933.34,3621.33) 1(1933.34,3621.33) 1(1933.34,3621.33)
  round 9.84 on Mech16: 1(925.22,3218.58) 1(925.22,3228.43) 1(1463.8,3218.58) 1(1463.8,3228.43)
  round 3.89 on Mech16: 1(951.78,2919.94) 1(951.78,2919.94) 1(951.78,2925.1) 1(951.78,2925.1) 1(951.78,2935.69) 1(951.78,2935.69) 1(951.78,2940.85) 1(951.78,2940.85) 1(951.78,2951.44) 1(951.78,2951.44) 1(951.78,2956.6) 1(951.78,2956.6) 1(951.78,2967.18) 1(951.78,2967.18) 1(951.78,2972.34) 1(951.78,2972.34) 1(951.78,2982.93) 1(951.78,2982.93) 1(951.78,2988.09) 1(951.78,2988.09) 1(951.78,2998.68) 1(951.78,2998.68) 1(951.78,3003.84) 1(951.78,3003.84) 1(951.78,3014.43) 1(951.78,3014.43) 1(951.78,3019.59) 1(951.78,3019.59) 1(951.78,3030.18) 1(951.78,3030.18) 1(951.78,3035.34) 1(951.78,3035.34) 1(951.78,3045.92) 1(951.78,3045.92) 1(951.78,3051.08) 1(951.78,3051.08) 1(951.78,3061.67) 1(951.78,3061.67) 1(951.78,3066.83) 1(951.78,3066.83) 1(951.78,3077.42) 1(951.78,3077.42) 1(951.78,3082.58) 1(951.78,3082.58) 1(951.78,3093.17) 1(951.78,3093.17) 1(951.78,3098.33) 1(951.78,3098.33) 1(951.78,3108.92) 1(951.78,3108.92) 1(951.78,3114.08) 1(951.78,3114.08) 1(951.78,3124.66) 1(951.78,3124.66) 1(951.78,3129.82) 1(951.78,3129.82) 1(951.78,3140.41) 1(951.78,3140.41) 1(951.78,3145.57) 1(951.78,3145.57) 1(951.78,3156.16) 1(951.78,3156.16) 1(951.78,3161.32) 1(951.78,3161.32) 1(951.78,3171.91) 1(951.78,3171.91) 1(951.78,3177.07) 1(951.78,3177.07) 1(951.78,3187.66) 1(951.78,3187.66) 1(951.78,3192.82) 1(951.78,3192.82) 1(951.78,3203.4) 1(951.78,3203.4) 1(951.78,3208.57) 1(951.78,3208.57) 1(951.78,3219.15) 1(951.78,3219.15) 1(951.78,3224.31) 1(951.78,3224.31) 1(978.59,2919.94) 1(978.59,2919.94) 1(978.59,2925.1) 1(978.59,2925.1) 1(978.59,2935.69) 1(978.59,2935.69) 1(978.59,2940.85) 1(978.59,2940.85) 1(978.59,2951.44) 1(978.59,2951.44) 1(978.59,2956.6) 1(978.59,2956.6) 1(978.59,2967.18) 1(978.59,2967.18) 1(978.59,2972.34) 1(978.59,2972.34) 1(978.59,2982.93) 1(978.59,2982.93) 1(978.59,2988.09) 1(978.59,2988.09) 1(978.59,2998.68) 1(978.59,2998.68) 1(978.59,3003.84) 1(978.59,3003.84) 1(978.59,3014.43) 1(978.59,3014.43) 1(978.59,3019.59) 1(978.59,3019.59) 1(978.59,3030.18) 1(978.59,3030.18) 1(978.59,3035.34) 1(978.59,3035.34) 1(978.59,3045.92) 1(978.59,3045.92) 1(978.59,3051.08) 1(978.59,3051.08) 1(978.59,3061.67) 1(978.59,3061.67) 1(978.59,3066.83) 1(978.59,3066.83) 1(978.59,3077.42) 1(978.59,3077.42) 1(978.59,3082.58) 1(978.59,3082.58) 1(978.59,3093.17) 1(978.59,3093.17) 1(978.59,3098.33) 1(978.59,3098.33) 1(978.59,3108.92) 1(978.59,3108.92) 1(978.59,3114.08) 1(978.59,3114.08) 1(978.59,3124.66) 1(978.59,3124.66) 1(978.59,3129.82) 1(978.59,3129.82) 1(978.59,3140.41) 1(978.59,3140.41) 1(978.59,3145.57) 1(978.59,3145.57) 1(978.59,3156.16) 1(978.59,3156.16) 1(978.59,3161.32) 1(978.59,3161.32) 1(978.59,3171.91) 1(978.59,3171.91) 1(978.59,3177.07) 1(978.59,3177.07) 1(978.59,3187.66) 1(978.59,3187.66) 1(978.59,3192.82) 1(978.59,3192.82) 1(978.59,3203.4) 1(978.59,3203.4) 1(978.59,3208.57) 1(978.59,3208.57) 1(978.59,3219.15) 1(978.59,3219.15) 1(978.59,3224.31) 1(978.59,3224.31) 1(1102.17,2919.94) 1(1102.17,2919.94) 1(1102.17,2925.1) 1(1102.17,2925.1) 1(1102.17,2935.69) 1(1102.17,2935.69) 1(1102.17,2940.85) 1(1102.17,2940.85) 1(1102.17,2951.44) 1(1102.17,2951.44) 1(1102.17,2956.6) 1(1102.17,2956.6) 1(1102.17,2967.18) 1(1102.17,2967.18) 1(1102.17,2972.34) 1(1102.17,2972.34) 1(1102.17,2982.93) 1(1102.17,2982.93) 1(1102.17,2988.09) 1(1102.17,2988.09) 1(1102.17,2998.68) 1(1102.17,2998.68) 1(1102.17,3003.84) 1(1102.17,3003.84) 1(1102.17,3014.43) 1(1102.17,3014.43) 1(1102.17,3019.59) 1(1102.17,3019.59) 1(1102.17,3030.18) 1(1102.17,3030.18) 1(1102.17,3035.34) 1(1102.17,3035.34) 1(1102.17,3045.92) 1(1102.17,3045.92) 1(1102.17,3051.08) 1(1102.17,3051.08) 1(1102.17,3061.67) 1(1102.17,3061.67) 1(1102.17,3066.83) 1(1102.17,3066.83) 1(1102.17,3077.42) 1(1102.17,3077.42) 1(1102.17,3082.58) 1(1102.17,3082.58) 1(1102.17,3093.17) 1(1102.17,3093.17) 1(1102.17,3098.33) 1(1102.17,3098.33) 1(1102.17,3108.92) 1(1102.17,3108.92) 1(1102.17,3114.08) 1(1102.17,3114.08) 1(1102.17,3124.66) 1(1102.17,3124.66) 1(1102.17,3129.82) 1(1102.17,3129.82) 1(1102.17,3140.41) 1(1102.17,3140.41) 1(1102.17,3145.57) 1(1102.17,3145.57) 1(1102.17,3156.16) 1(1102.17,3156.16) 1(1102.17,3161.32) 1(1102.17,3161.32) 1(1102.17,3171.91) 1(1102.17,3171.91) 1(1102.17,3177.07) 1(1102.17,3177.07) 1(1102.17,3187.66) 1(1102.17,3187.66) 1(1102.17,3192.82) 1(1102.17,3192.82) 1(1102.17,3203.4) 1(1102.17,3203.4) 1(1102.17,3208.57) 1(1102.17,3208.57) 1(1102.17,3219.15) 1(1102.17,3219.15) 1(1102.17,3224.31) 1(1102.17,3224.31) 1(1128.99,2919.94) 1(1128.99,2919.94) 1(1128.99,2925.1) 1(1128.99,2925.1) 1(1128.99,2935.69) 1(1128.99,2935.69) 1(1128.99,2940.85) 1(1128.99,2940.85) 1(1128.99,2951.44) 1(1128.99,2951.44) 1(1128.99,2956.6) 1(1128.99,2956.6) 1(1128.99,2967.18) 1(1128.99,2967.18) 1(1128.99,2972.34) 1(1128.99,2972.34) 1(1128.99,2982.93) 1(1128.99,2982.93) 1(1128.99,2988.09) 1(1128.99,2988.09) 1(1128.99,2998.68) 1(1128.99,2998.68) 1(1128.99,3003.84) 1(1128.99,3003.84) 1(1128.99,3014.43) 1(1128.99,3014.43) 1(1128.99,3019.59) 1(1128.99,3019.59) 1(1128.99,3030.18) 1(1128.99,3030.18) 1(1128.99,3035.34) 1(1128.99,3035.34) 1(1128.99,3045.92) 1(1128.99,3045.92) 1(1128.99,3051.08) 1(1128.99,3051.08) 1(1128.99,3061.67) 1(1128.99,3061.67) 1(1128.99,3066.83) 1(1128.99,3066.83) 1(1128.99,3077.42) 1(1128.99,3077.42) 1(1128.99,3082.58) 1(1128.99,3082.58) 1(1128.99,3093.17) 1(1128.99,3093.17) 1(1128.99,3098.33) 1(1128.99,3098.33) 1(1128.99,3108.92) 1(1128.99,3108.92) 1(1128.99,3114.08) 1(1128.99,3114.08) 1(1128.99,3124.66) 1(1128.99,3124.66) 1(1128.99,3129.82) 1(1128.99,3129.82) 1(1128.99,3140.41) 1(1128.99,3140.41) 1(1128.99,3145.57) 1(1128.99,3145.57) 1(1128.99,3156.16) 1(1128.99,3156.16) 1(1128.99,3161.32) 1(1128.99,3161.32) 1(1128.99,3171.91) 1(1128.99,3171.91) 1(1128.99,3177.07) 1(1128.99,3177.07) 1(1128.99,3187.66) 1(1128.99,3187.66) 1(1128.99,3192.82) 1(1128.99,3192.82) 1(1128.99,3203.4) 1(1128.99,3203.4) 1(1128.99,3208.57) 1(1128.99,3208.57) 1(1128.99,3219.15) 1(1128.99,3219.15) 1(1128.99,3224.31) 1(1128.99,3224.31) 1(1490.35,2919.94) 1(1490.35,2919.94) 1(1490.35,2925.1) 1(1490.35,2925.1) 1(1490.35,2935.69) 1(1490.35,2935.69) 1(1490.35,2940.85) 1(1490.35,2940.85) 1(1490.35,2951.44) 1(1490.35,2951.44) 1(1490.35,2956.6) 1(1490.35,2956.6) 1(1490.35,2967.18) 1(1490.35,2967.18) 1(1490.35,2972.34) 1(1490.35,2972.34) 1(1490.35,2982.93) 1(1490.35,2982.93) 1(1490.35,2988.09) 1(1490.35,2988.09) 1(1490.35,2998.68) 1(1490.35,2998.68) 1(1490.35,3003.84) 1(1490.35,3003.84) 1(1490.35,3014.43) 1(1490.35,3014.43) 1(1490.35,3019.59) 1(1490.35,3019.59) 1(1490.35,3030.18) 1(1490.35,3030.18) 1(1490.35,3035.34) 1(1490.35,3035.34) 1(1490.35,3045.92) 1(1490.35,3045.92) 1(1490.35,3051.08) 1(1490.35,3051.08) 1(1490.35,3061.67) 1(1490.35,3061.67) 1(1490.35,3066.83) 1(1490.35,3066.83) 1(1490.35,3077.42) 1(1490.35,3077.42) 1(1490.35,3082.58) 1(1490.35,3082.58) 1(1490.35,3093.17) 1(1490.35,3093.17) 1(1490.35,3098.33) 1(1490.35,3098.33) 1(1490.35,3108.92) 1(1490.35,3108.92) 1(1490.35,3114.08) 1(1490.35,3114.08) 1(1490.35,3124.66) 1(1490.35,3124.66) 1(1490.35,3129.82) 1(1490.35,3129.82) 1(1490.35,3140.41) 1(1490.35,3140.41) 1(1490.35,3145.57) 1(1490.35,3145.57) 1(1490.35,3156.16) 1(1490.35,3156.16) 1(1490.35,3161.32) 1(1490.35,3161.32) 1(1490.35,3171.91) 1(1490.35,3171.91) 1(1490.35,3177.07) 1(1490.35,3177.07) 1(1490.35,3187.66) 1(1490.35,3187.66) 1(1490.35,3192.82) 1(1490.35,3192.82) 1(1490.35,3203.4) 1(1490.35,3203.4) 1(1490.35,3208.57) 1(1490.35,3208.57) 1(1490.35,3219.15) 1(1490.35,3219.15) 1(1490.35,3224.31) 1(1490.35,3224.31) 1(1517.17,2919.94) 1(1517.17,2919.94) 1(1517.17,2925.1) 1(1517.17,2925.1) 1(1517.17,2935.69) 1(1517.17,2935.69) 1(1517.17,2940.85) 1(1517.17,2940.85) 1(1517.17,2951.44) 1(1517.17,2951.44) 1(1517.17,2956.6) 1(1517.17,2956.6) 1(1517.17,2967.18) 1(1517.17,2967.18) 1(1517.17,2972.34) 1(1517.17,2972.34) 1(1517.17,2982.93) 1(1517.17,2982.93) 1(1517.17,2988.09) 1(1517.17,2988.09) 1(1517.17,2998.68) 1(1517.17,2998.68) 1(1517.17,3003.84) 1(1517.17,3003.84) 1(1517.17,3014.43) 1(1517.17,3014.43) 1(1517.17,3019.59) 1(1517.17,3019.59) 1(1517.17,3030.18) 1(1517.17,3030.18) 1(1517.17,3035.34) 1(1517.17,3035.34) 1(1517.17,3045.92) 1(1517.17,3045.92) 1(1517.17,3051.08) 1(1517.17,3051.08) 1(1517.17,3061.67) 1(1517.17,3061.67) 1(1517.17,3066.83) 1(1517.17,3066.83) 1(1517.17,3077.42) 1(1517.17,3077.42) 1(1517.17,3082.58) 1(1517.17,3082.58) 1(1517.17,3093.17) 1(1517.17,3093.17) 1(1517.17,3098.33) 1(1517.17,3098.33) 1(1517.17,3108.92) 1(1517.17,3108.92) 1(1517.17,3114.08) 1(1517.17,3114.08) 1(1517.17,3124.66) 1(1517.17,3124.66) 1(1517.17,3129.82) 1(1517.17,3129.82) 1(1517.17,3140.41) 1(1517.17,3140.41) 1(1517.17,3145.57) 1(1517.17,3145.57) 1(1517.17,3156.16) 1(1517.17,3156.16) 1(1517.17,3161.32) 1(1517.17,3161.32) 1(1517.17,3171.91) 1(1517.17,3171.91) 1(1517.17,3177.07) 1(1517.17,3177.07) 1(1517.17,3187.66) 1(1517.17,3187.66) 1(1517.17,3192.82) 1(1517.17,3192.82) 1(1517.17,3203.4) 1(1517.17,3203.4) 1(1517.17,3208.57) 1(1517.17,3208.57) 1(1517.17,3219.15) 1(1517.17,3219.15) 1(1517.17,3224.31) 1(1517.17,3224.31) 1(1640.75,2919.94) 1(1640.75,2919.94) 1(1640.75,2925.1) 1(1640.75,2925.1) 1(1640.75,2935.69) 1(1640.75,2935.69) 1(1640.75,2940.85) 1(1640.75,2940.85) 1(1640.75,2951.44) 1(1640.75,2951.44) 1(1640.75,2956.6) 1(1640.75,2956.6) 1(1640.75,2967.18) 1(1640.75,2967.18) 1(1640.75,2972.34) 1(1640.75,2972.34) 1(1640.75,2982.93) 1(1640.75,2982.93) 1(1640.75,2988.09) 1(1640.75,2988.09) 1(1640.75,2998.68) 1(1640.75,2998.68) 1(1640.75,3003.84) 1(1640.75,3003.84) 1(1640.75,3014.43) 1(1640.75,3014.43) 1(1640.75,3019.59) 1(1640.75,3019.59) 1(1640.75,3030.18) 1(1640.75,3030.18) 1(1640.75,3035.34) 1(1640.75,3035.34) 1(1640.75,3045.92) 1(1640.75,3045.92) 1(1640.75,3051.08) 1(1640.75,3051.08) 1(1640.75,3061.67) 1(1640.75,3061.67) 1(1640.75,3066.83) 1(1640.75,3066.83) 1(1640.75,3077.42) 1(1640.75,3077.42) 1(1640.75,3082.58) 1(1640.75,3082.58) 1(1640.75,3093.17) 1(1640.75,3093.17) 1(1640.75,3098.33) 1(1640.75,3098.33) 1(1640.75,3108.92) 1(1640.75,3108.92) 1(1640.75,3114.08) 1(1640.75,3114.08) 1(1640.75,3124.66) 1(1640.75,3124.66) 1(1640.75,3129.82) 1(1640.75,3129.82) 1(1640.75,3140.41) 1(1640.75,3140.41) 1(1640.75,3145.57) 1(1640.75,3145.57) 1(1640.75,3156.16) 1(1640.75,3156.16) 1(1640.75,3161.32) 1(1640.75,3161.32) 1(1640.75,3171.91) 1(1640.75,3171.91) 1(1640.75,3177.07) 1(1640.75,3177.07) 1(1640.75,3187.66) 1(1640.75,3187.66) 1(1640.75,3192.82) 1(1640.75,3192.82) 1(1640.75,3203.4) 1(1640.75,3203.4) 1(1640.75,3208.57) 1(1640.75,3208.57) 1(1640.75,3219.15) 1(1640.75,3219.15) 1(1640.75,3224.31) 1(1640.75,3224.31) 1(1667.56,2919.94) 1(1667.56,2919.94) 1(1667.56,2925.1) 1(1667.56,2925.1) 1(1667.56,2935.69) 1(1667.56,2935.69) 1(1667.56,2940.85) 1(1667.56,2940.85) 1(1667.56,2951.44) 1(1667.56,2951.44) 1(1667.56,2956.6) 1(1667.56,2956.6) 1(1667.56,2967.18) 1(1667.56,2967.18) 1(1667.56,2972.34) 1(1667.56,2972.34) 1(1667.56,2982.93) 1(1667.56,2982.93) 1(1667.56,2988.09) 1(1667.56,2988.09) 1(1667.56,2998.68) 1(1667.56,2998.68) 1(1667.56,3003.84) 1(1667.56,3003.84) 1(1667.56,3014.43) 1(1667.56,3014.43) 1(1667.56,3019.59) 1(1667.56,3019.59) 1(1667.56,3030.18) 1(1667.56,3030.18) 1(1667.56,3035.34) 1(1667.56,3035.34) 1(1667.56,3045.92) 1(1667.56,3045.92) 1(1667.56,3051.08) 1(1667.56,3051.08) 1(1667.56,3061.67) 1(1667.56,3061.67) 1(1667.56,3066.83) 1(1667.56,3066.83) 1(1667.56,3077.42) 1(1667.56,3077.42) 1(1667.56,3082.58) 1(1667.56,3082.58) 1(1667.56,3093.17) 1(1667.56,3093.17) 1(1667.56,3098.33) 1(1667.56,3098.33) 1(1667.56,3108.92) 1(1667.56,3108.92) 1(1667.56,3114.08) 1(1667.56,3114.08) 1(1667.56,3124.66) 1(1667.56,3124.66) 1(1667.56,3129.82) 1(1667.56,3129.82) 1(1667.56,3140.41) 1(1667.56,3140.41) 1(1667.56,3145.57) 1(1667.56,3145.57) 1(1667.56,3156.16) 1(1667.56,3156.16) 1(1667.56,3161.32) 1(1667.56,3161.32) 1(1667.56,3171.91) 1(1667.56,3171.91) 1(1667.56,3177.07) 1(1667.56,3177.07) 1(1667.56,3187.66) 1(1667.56,3187.66) 1(1667.56,3192.82) 1(1667.56,3192.82) 1(1667.56,3203.4) 1(1667.56,3203.4) 1(1667.56,3208.57) 1(1667.56,3208.57) 1(1667.56,3219.15) 1(1667.56,3219.15) 1(1667.56,3224.31) 1(1667.56,3224.31)
  round 6 on Mech16: 1(969.94,2737.13) 1(969.94,3406.42) 1(970.3,2737.37) 1(970.3,3406.67) 1(1009.31,2776.5) 1(1009.31,3367.05) 1(1009.67,2776.74) 1(1009.67,3367.3) 1(1226.2,2678.63) 1(1226.2,3465.41) 1(1226.2,2678.63) 1(1226.2,2737.37) 1(1226.2,2737.37) 1(1226.2,3406.67) 1(1226.2,3406.67) 1(1226.2,3465.41) 1(1383.68,2678.63) 1(1383.68,2737.37) 1(1383.68,2737.37) 1(1383.68,3406.67) 1(1383.68,3406.67) 1(1383.68,3465.41) 1(1383.68,2678.63) 1(1383.68,3465.41) 1(1600.22,2776.74) 1(1600.22,2776.74) 1(1600.22,3367.3) 1(1600.22,3367.3) 1(1639.59,2737.37) 1(1639.59,2737.37) 1(1639.59,3406.67) 1(1639.59,3406.67)
  round 65 on Mech16: 1(1304.94,2678.32) 1(1304.94,2678.32) 1(1304.94,2678.32) 1(1304.94,3465.72) 1(1304.94,3465.72) 1(1304.94,3465.72)

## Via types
v1: diameter 16, hole 8, L1-Top Layer to L10-Bottom Layer, tented both sides, 414 vias
v2: diameter 12, hole 6, L1-Top Layer to L10-Bottom Layer, tented both sides, 243 vias
v3: diameter 19.68, hole 7.87, L1-Top Layer to L10-Bottom Layer, 44 vias
v4: diameter 14, hole 6, L1-Top Layer to L10-Bottom Layer, tented both sides, 2 vias
v5: diameter 16, hole 8, L1-Top Layer to L10-Bottom Layer, tented top, 1 vias
v6: diameter 20, hole 10, L1-Top Layer to L10-Bottom Layer, tented both sides, 1 vias

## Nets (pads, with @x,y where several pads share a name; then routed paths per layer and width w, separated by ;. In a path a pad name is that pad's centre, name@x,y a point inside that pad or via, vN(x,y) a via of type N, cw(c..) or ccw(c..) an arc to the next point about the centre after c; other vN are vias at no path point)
AGND: C1.2 C2.2 C9.2 C12.1 R7.1 U2.B3 | length 190.4
  L1-Top Layer w8: 400,1950.6 403.33,1953.93 U2.B3@412.32,1953.93
  L1-Top Layer w15: C1.2@342.62,2035.83 v1(342.62,2067.45) ; v1(344.31,1826.11) 344.31,1855.45 C2.2@344.93,1856.07 ; v1(408,1831) R7.1@408.07,1858 ; R7.1@408.07,1858 R7.1@408.07,1858 ; v2(412.36,1881.36) 408,1877 R7.1@408.07,1858 ; C12.1@539.68,1990 v1(563.82,1990) ; C9.2@564.2,1944.34 591.31,1971.44 v2(591.31,1971.6)
  other v1: 329.77,1945.27
AU_AOL: AOL.1 C10.2 CN6.N10 | length 1632.6
  L1-Top Layer w5.5: AOL.1@496.71,1757.43 496.71,1775.71 497.31,1776.31 v2(497.31,1805.11) C10.2@497.31,1831.47
  L1-Top Layer w10: v2(1411.18,2559.36) CN6.N10@1423.41,2547.13
  L10-Bottom Layer w5.5: v2(497.31,1805.11) 497.31,1987.31 552,2042 552,2366.35 683.79,2498.14 936.85,2498.14 987.25,2548.54 1120.31,2548.54 1152.82,2581.04 1230.96,2581.04 1236.62,2575.38 1275.76,2575.38 1276.26,2574.88 1395.67,2574.88 v2(1411.18,2559.36)
AU_AOM: AOM.1 CN6.M11 | length 195.6
  L1-Top Layer w5.5: AOM.1@1251.07,2575 1257.45,2581.38 1374.53,2581.38 1385.32,2570.59 1385.32,2541.3 1397.82,2528.8 CN6.M11@1397.82,2521.54
AU_MBIAS: C17.2 CN6.N13 MBIAS.1 R14.2 | length 1010.3
  L1-Top Layer w5.5: R14.2@631.34,2229.42 631.34,2301.92 C17.2@625.96,2307.3 598.32,2334.94 598.32,2395.4 644.92,2442 860.81,2442 MBIAS.1@883,2419.81 ; MBIAS.1@883,2421 904,2442 1100.79,2442 1162.62,2503.84 1205.85,2503.84 1224.64,2522.62 1283.2,2522.62 1309.57,2549 1344.77,2549 CN6.N13@1346.64,2547.13
AU_MIC_IN: C15.1 CN6.N12 | length 1047.9
  L1-Top Layer w5.5: C15.1@576.34,2245.29 576.34,2400.99 636.85,2461.5 1091.92,2461.5 1094.71,2464.29 1094.93,2464.29 1153.98,2523.34 1197.78,2523.34 1216.56,2542.12 1270.32,2542.12 1299.57,2571.38 1358.66,2571.38 1358.79,2571.25 1371.23,2571.25 1374.81,2567.67 1374.81,2549.71 CN6.N12@1372.23,2547.13
AU_SHDN: CN6.A9 R5.1 SHDN.1 | length 1517.6
  L1-Top Layer w5.5: R5.1@446.62,2073 450,2076.38 SHDN.1@450,2147.39 513.61,2147.39 536.44,2124.56 v1(598.23,2124.56) ; v2@1436.77,2252.28 CN6.A9@1449,2240.05
  L10-Bottom Layer w5: 1398.09,2301.53 1398.09,2273.3 1405.39,2266 1431.63,2266 1436.77,2260.86 v2(1436.77,2253.41)
  L10-Bottom Layer w5.5: v1(598.23,2124.56) 598.78,2124.56 738.33,1985 1124.54,1985 1129.79,1990.25 1129.79,2021.44 1129.52,2021.71 1129.52,2090.7 1160.06,2121.24 1160.06,2281.36 1177.45,2298.74 1247.12,2298.74 1253,2304.62 1278.03,2304.62 1301.13,2327.73 1301.13,2339.13 1310.44,2348.44 1351.18,2348.44 1398.09,2301.53
AU_VMID: C38.1 C39.2 CN6.N11 VMID.1 | length 437.4
  L1-Top Layer w5: VMID.1@1139.2,2666 1139.96,2666.76 v2(1172.38,2666.76)
  L1-Top Layer w9: C38.1@1384.7,2654.88 1396.55,2643.03 C39.2@1396.55,2610.4 ; 1396.57,2565.22 1396.57,2548.38 CN6.N11@1397.82,2547.13 ; 1397.79,2566.5 C39.2@1397.79,2611.43
  L1-Top Layer w10: C38.1@1384.7,2654.88 v2(1384.7,2689.19)
  L10-Bottom Layer w5: v2(1172.38,2666.76) 1172.38,2688.12 1200.65,2716.39 1357.09,2716.39 1384.3,2689.19 v2(1384.7,2689.19)
AU_VREF: C108.2 C109.1 CN6.M12 FB8.2 VREF_AU.1 | length 647.5
  L1-Top Layer w6: v2@1335.55,2536.58 1338.37,2533.77 1351.74,2533.77 1363.97,2521.54 CN6.M12@1372.23,2521.54
  L1-Top Layer w10: v1@961.78,2403.22 962,2403.43 v1(962,2408) ; VREF_AU.1@962.44,2336.15 v1@962.44,2402.56
  L10-Bottom Layer w10: v1(962,2408) 962,2439.06 961.78,2439.28 975.5,2453 1129.32,2453 1144.22,2438.1 1230.59,2438.1 C109.1@1263.5,2471 ; FB8.2@1261.69,2526 1261.69,2472.81 C109.1@1263.5,2471 ; v2(1335,2536.03) 1337.01,2534.02 C108.2@1337.01,2505.82 1336.43,2505.82 1301.61,2471 C109.1@1263.5,2471
BOOT0: CN6.A7 R96.1 SW3.4 | length 1317.9
  L1-Top Layer w5: v2@1476,2196 1476.71,2196.71 1476.71,2208.39 1500.18,2231.86 CN6.A7@1500.18,2240.05 ; v1(1884,1454) 1884,1407.84 1927.32,1364.52 SW3.4@1985.83,1364.52
  L8-SIG2 w4.5: v2@1476,2196 1476,2152.98 1452.6,2129.58 1452.6,2063.31 1455.62,2060.3 1455.62,2008.71 1565.91,1898.41 1565.91,1729.11 1841.02,1454 v1(1884,1454)
  L10-Bottom Layer w5: v1(1884,1454) 1884,1427 1938,1373 R96.1@1977,1373
  other v2: 1476.46,2195
BOOT1: CN6.B7 R97.1 SW3.5 | length 1192.6
  L1-Top Layer w5: v2@1492.15,2183 1492.92,2183.76 1492.92,2210.92 1514.25,2232.26 1514.25,2251.57 CN6.B7@1500.18,2265.64 ; v1(1937.5,1409) 1985.83,1409 SW3.5@1985.83,1403.89
  L8-SIG2 w4.5: v2@1492.15,2183 1492.15,2081.15 1470,2059 1470,2021 1586.54,1904.46 1586.54,1748.65 1848.19,1487 1893,1487 1937.5,1442.5 v1(1937.5,1409)
  L10-Bottom Layer w5: v1(1937.5,1409) R97.1@1976.02,1409
  other v2: 1492.45,2181
BOOT2: CN6.C7 R98.1 SW3.6 | length 1286.3
  L1-Top Layer w5: v2@1457.2,2204.45 1457.97,2204.45 1488,2234.47 1488,2279.05 CN6.C7@1500.18,2291.23 ; v1(1913.12,1436) 1920.39,1443.26 SW3.6@1985.83,1443.26
  L8-SIG2 w4.5: v2@1457.2,2204.45 v2@1459,2202.65 ; v2@1459,2205.47 v2@1459,2202.65 ; v1(1913.12,1436) 1909.47,1436 1906.47,1439 1816.57,1439 1487.18,1768.39 1487.18,1948.09 1428.87,2006.4 1428.87,2122.13 1459,2152.26 v2@1459,2202.65
  L10-Bottom Layer w5: v1(1913.12,1436) 1967.47,1436 R98.1@1975.47,1444
  other v2: 1460.2,2204.45
CK_XI: C53.2 CN6.G1 R63.1 Y1.1 | length 252
  L1-Top Layer w4: CN6.G1@1653.72,2393.59 1690.4,2393.59 1738.36,2441.55 Y1.1@1738.36,2443.67 1738.36,2446.76 1763.6,2472 1796.13,2472 1815,2453.13 R63.1@1815,2449.62 1825.7,2460.32 C53.2@1854.44,2460.32
CK_XO: C54.2 CN6.G2 R63.2 Y1.3 | length 247.7
  L1-Top Layer w4: CN6.G2@1628.13,2393.59 1642.01,2379.72 1750.34,2379.72 1769.86,2399.24 Y1.3@1769.86,2402.33 1810.32,2402.33 1812.16,2400.49 C54.2@1858.11,2400.49
DDR_VREF: C48.2 C50.2 C51.1 C52.1 C75.2 CN6.A4 CN6.D1 R104.1 R113.2 VREF.1 | length 923.5
  L1-Top Layer w10: CN6.A4@1576.95,2240.05 1578.41,2238.59 1578.41,2178.96 v2@1578.86,2178.52 ; CN6.D1@1653.72,2316.82 1662.69,2307.86 v2(1687.56,2307.86) 1710.7,2331 C48.2@1739.51,2331 1740.27,2331 1740.27,2308.9 1759.82,2289.36 1838.11,2289.36 C51.1@1839.38,2290.62 ; v2(1828,2314.61) 1828,2303.72 1839.38,2292.34 C51.1@1839.38,2290.62 ; C51.1@1840.26,2291.5 C51.1@1839.38,2290.62 ; C51.1@1844.14,2292.34 1844.14,2310.14 v2(1848.11,2314.11) ; v1@1921.84,2127 v1@1922.55,2127 ; VREF.1@2056.14,2285.51 VREF.1@2051,2285.51 1926.04,2285.51 1882.87,2242.34 C50.2@1820,2242.34 1820,2254.21 1839.38,2273.59 C51.1@1839.38,2290.62
  L8-SIG2 w10: 1805.84,2129.07 1811.12,2123.79 1918.14,2123.79 v1(1920.38,2126.03)
  L10-Bottom Layer w4: v2(1687.56,2307.86) v2@1687.81,2308.11
  L10-Bottom Layer w10: v2@1578.86,2172.7 1578.86,2154.24 1577,2152.38 R113.2@1586.38,2143 ; v2@1687.81,2308.11 1703.7,2324 1732.51,2324 C75.2@1739.51,2331 ; v2(1828,2314.61) 1828,2304.72 R104.1@1840.38,2292.34 1842.34,2292.34 1848.11,2298.11 v2(1848.11,2314.11)
  other v2: 1579.1,2172.7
